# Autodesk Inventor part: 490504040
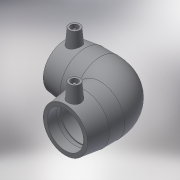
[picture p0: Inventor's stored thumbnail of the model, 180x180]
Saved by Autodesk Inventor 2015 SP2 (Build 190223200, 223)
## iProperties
Created: 2017-06
Part Number: 490504040
Material: Generic
Description: PLASSON 90° ELBOW 40
Document SubType Name: Modeling
Designer: KIM
Mass: 55.0731 g
Surface Area: 148.067 cm^2
Volume: 55.0731 cm^3
Density: 1 g/cm^3
Appearance: Default
Author: KIM
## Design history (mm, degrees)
derived "490504.ipt"
feature "Solid1::490504.ipt"
tag "TaggingFeature1"
body "Solid1"
other parameters: "d2" = 55, "d4" = 23, "d5" = 49.5, "d8" = 168 deg, "d10" = 17.6, "d11" = 5.86667, "d14" = 17.6296, "d19" = 3.52592, "d20" = 168 deg, "d22" = 50.6, "d23" = 55, "d24" = 49.082, "d29" = 47, "d30" = 15, "d31" = 55.2, "d34" = 5 deg, "d35" = 15, "d39" = 5 deg, "d41" = 4, "d42" = 14, "d43" = 0, "d45" = 4, "d46" = 14, "d47" = 0, "d50" = 34, "d51" = 17.6, "d52" = 44, "d54" = 90 deg, "d67" = 45 deg, "d71" = 90 deg, "d75" = 2.75, "d82" = 45 deg, "d83" = 44, "d84" = 49.5, "d86" = 24.75, "d87" = 90 deg, "d90" = 44, "d91" = 0, "d92" = 44, "d93" = 0, "d94" = 90 deg, "d95" = 25.3, "d98" = 92, "d101" = 3, "d102" = 0, "d103" = 3, "d104" = 0, "d105" = 12.76, "d106" = 3.19, "d107" = 92, "d110" = 24.2, "L_" = 92, "L_1" = 44, "D_" = 55, "A_" = 47, "d_2" = 12
